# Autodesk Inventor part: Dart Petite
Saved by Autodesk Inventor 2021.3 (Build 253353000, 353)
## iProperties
Created: 2022-09
Part Number: Dart Petite
Material: Generic
Document SubType Name: Modeling
Designer: Administrator
Density: 1 g/cm^3
Appearance: Default
Title: Dart Petite
Author: Administrator
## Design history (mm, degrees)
feature "Glass-Dart Petite"
body "Solid1"
